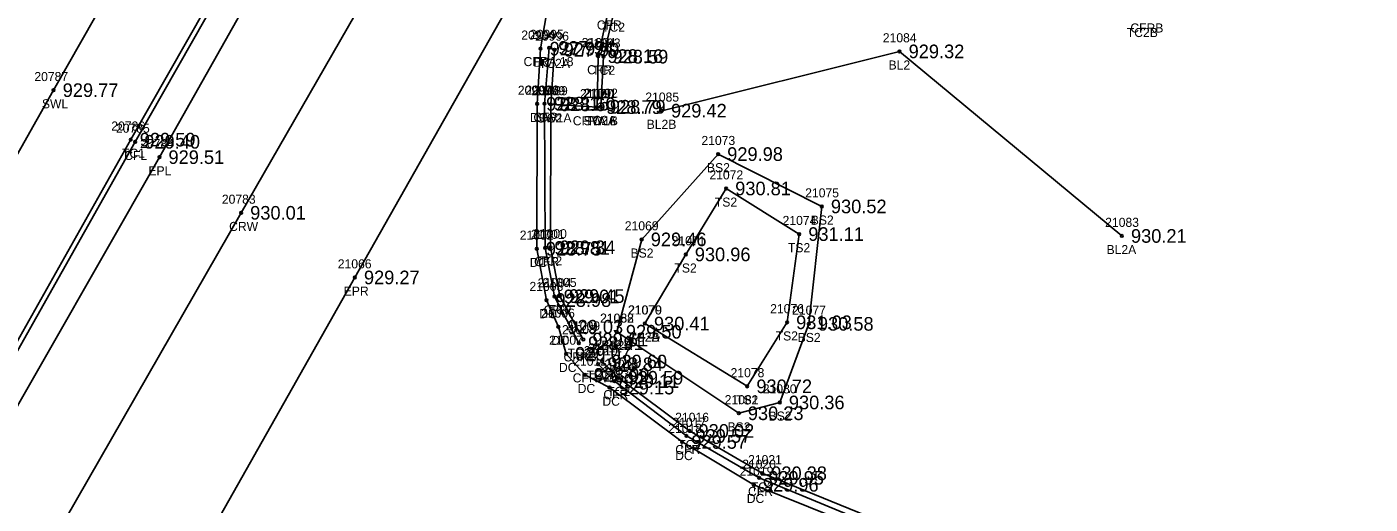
# Model space of a CAD drawing. Extents: x 1576181 to 1577685, y 1099396 to 1101490.
# Drawn here: x 1576724.5 to 1576872.4, y 1100126.4 to 1100179 of the extents above; entities that cross this region are included whole.
import ezdxf

# ---------------------------------------------------------------- set-up
doc = ezdxf.new("R2010")
doc.units = 0
for name, color, linetype in [('RD_DTM_BkLn1', 7, 'Continuous'), ('RD_DTM_BkLn2', 7, 'Continuous'), ('RD_DTM_BkLn_txCode', 7, 'Continuous'), ('RD_EX_Conc', 7, 'Continuous'), ('RD_EX_Conc_txCode', 7, 'Continuous'), ('RD_EX_Road', 7, 'Continuous'), ('RD_EX_Road_txCode', 7, 'Continuous'), ('RD_EX_TX_Conc_ELEV', 7, 'Continuous'), ('RD_EX_TX_Misc_ELEV', 7, 'Continuous'), ('RD_EX_TX_Road_ELEV', 7, 'Continuous'), ('RD_HC_Survey_ELEV', 7, 'Continuous'), ('RD_HC_Survey_txCode', 7, 'Continuous'), ('RD_SMD_Locator', 7, 'Continuous')]:
    doc.layers.add(name, color=color, linetype=linetype)

msp = doc.modelspace()

# ---------------------------------------------------------------- linework, layer by layer
at = {"layer": 'RD_DTM_BkLn1'}
for points in [[(1576435.96, 1099635.47), (1576469.98, 1099685.91), (1576496.51, 1099728.46), (1576522.67, 1099770.85), (1576549.06, 1099813.4), (1576563.36, 1099837.2), (1576575.09, 1099855.95), (1576600.75, 1099898.96), (1576625.57, 1099942.14), (1576652.37, 1099988.91), (1576675.03, 1100029.12), (1576699.51, 1100072.44), (1576723.52, 1100115.7), (1576748.08, 1100158.53), (1576774.13, 1100203.85), (1576797.97, 1100246.52), (1576822.46, 1100289.82), (1576846.93, 1100333.35), (1576871.37, 1100376.46), (1576888.27, 1100406.22)], [(1576845.09, 1100155.98), (1576820.6, 1100176.31), (1576794.43, 1100169.78)]]:
    msp.add_lwpolyline(points, dxfattribs=at)
at = {"layer": 'RD_DTM_BkLn2'}
for points in [[(1576569.71, 1099889.13), (1576574.56, 1099891.34), (1576579.27, 1099894.47), (1576584.19, 1099899.55), (1576592.25, 1099913.59), (1576612.84, 1099949.87), (1576637.54, 1099993.05), (1576637.54, 1099993.05), (1576662.19, 1100036.34), (1576686.67, 1100079.69), (1576711.46, 1100123.12), (1576735.92, 1100166.59), (1576760.76, 1100210.19), (1576785.21, 1100253.55), (1576809.13, 1100296.43), (1576833.85, 1100340.61), (1576852.06, 1100373.52), (1576858.66, 1100385.37)], [(1576787.7, 1100170.21), (1576787.99, 1100175.73), (1576789.09, 1100180.48), (1576790.59, 1100185.09)], [(1576782.61, 1100176.49), (1576782.18, 1100170.48), (1576782.16, 1100154.73), (1576783.18, 1100149.36), (1576785.77, 1100144.57)], [(1576789.46, 1100145.43), (1576792.2, 1100155.6), (1576800.62, 1100165), (1576812.04, 1100159.23), (1576810.61, 1100146.3), (1576807.41, 1100137.64), (1576802.89, 1100136.45), (1576789.46, 1100145.43)], [(1576792.55, 1100146.33), (1576797.05, 1100153.95), (1576801.5, 1100161.21), (1576809.55, 1100156.19), (1576808.21, 1100146.47), (1576803.83, 1100139.42), (1576792.55, 1100146.33)], [(1576787.86, 1100142.15), (1576789.65, 1100140.36), (1576797.46, 1100134.51), (1576805.47, 1100129.84), (1576819.79, 1100124)]]:
    msp.add_lwpolyline(points, dxfattribs=at)
at = {"layer": 'RD_EX_Conc'}
msp.add_line((1576782.18, 1100170.48), (1576787.28, 1100170.17), dxfattribs=at)
for points in [[(1576592.25, 1099913.59), (1576580.2, 1099912.49), (1576604.17, 1099954.86), (1576628.85, 1099997.89), (1576628.85, 1099997.89), (1576652.81, 1100040.47), (1576678.28, 1100085.17), (1576702.19, 1100127.32), (1576727.43, 1100172.04), (1576752.1, 1100215.39), (1576776.49, 1100258.76), (1576788, 1100277.34), (1576801.96, 1100301.42), (1576820.18, 1100348.3), (1576829.19, 1100379.59), (1576833.87, 1100393.41), (1576838.32, 1100402.43), (1576861.82, 1100391.11)], [(1576569.87, 1099888.69), (1576574.84, 1099890.86), (1576574.84, 1099890.86), (1576579.65, 1099894.15), (1576584.72, 1099899.29), (1576592.68, 1099913.3), (1576613.45, 1099949.72), (1576638.02, 1099992.78), (1576638.02, 1099992.78), (1576662.6, 1100036.05), (1576687.14, 1100079.44), (1576711.91, 1100122.93), (1576736.42, 1100166.35), (1576761.24, 1100209.96), (1576785.67, 1100253.17), (1576809.57, 1100296.25), (1576834.31, 1100340.56), (1576852.46, 1100373.22), (1576852.46, 1100373.22), (1576859.24, 1100385.1)], [(1576785.78, 1100195.96), (1576786.17, 1100195.75), (1576783.4, 1100187.6), (1576781.94, 1100181.75), (1576781.06, 1100176.61), (1576780.68, 1100170.53), (1576780.65, 1100154.57), (1576781.71, 1100148.92), (1576783.02, 1100145.98), (1576783.87, 1100143), (1576785.93, 1100140.68), (1576788.65, 1100139.28), (1576796.67, 1100133.29), (1576804.55, 1100128.57), (1576819.43, 1100122.6)], [(1576787.28, 1100170.17), (1576787.42, 1100175.79), (1576788.49, 1100180.72), (1576790.08, 1100185.23)], [(1576782.01, 1100176.69), (1576781.51, 1100170.55), (1576781.58, 1100154.66), (1576782.61, 1100149.32), (1576785.29, 1100144.16)], [(1576787.42, 1100141.85), (1576789.21, 1100140), (1576797.13, 1100133.95), (1576805.14, 1100129.34), (1576819.69, 1100123.32)]]:
    msp.add_lwpolyline(points, dxfattribs=at)
at = {"layer": 'RD_EX_Road'}
for points in [[(1576574.84, 1099890.86), (1576581.17, 1099887.16), (1576595.39, 1099911.97), (1576615.87, 1099948.17), (1576640.56, 1099991.4), (1576640.56, 1099991.4), (1576664.88, 1100034.19), (1576689.84, 1100078.06), (1576714.22, 1100121.19), (1576739.08, 1100164.66), (1576764.15, 1100209.11), (1576788.31, 1100251.8), (1576812.15, 1100294.46), (1576837.06, 1100339.37), (1576855.38, 1100371.53), (1576853.98, 1100372.48), (1576862.98, 1100388.86), (1576865.16, 1100391.95), (1576873.15, 1100402.8), (1576877.45, 1100410.32)], [(1576663.31, 1099979.53), (1576687.43, 1100021.53), (1576712.03, 1100065.1), (1576738.42, 1100112.14), (1576760.61, 1100151.41), (1576785.78, 1100195.96), (1576800.59, 1100221.87), (1576817.54, 1100252.08), (1576858.25, 1100324.63), (1576880.45, 1100364.01), (1576883.5, 1100369.45), (1576896.98, 1100397.71)]]:
    msp.add_lwpolyline(points, dxfattribs=at)
at = {"layer": 'RD_SMD_Locator'}
for centre in [(1576781.06, 1100176.61), (1576782.01, 1100176.69), (1576782.61, 1100176.49), (1576820.6, 1100176.31), (1576787.42, 1100175.79), (1576787.99, 1100175.73), (1576727.43, 1100172.04), (1576780.68, 1100170.53), (1576781.51, 1100170.55), (1576782.18, 1100170.48), (1576782.18, 1100170.48), (1576787.28, 1100170.17), (1576787.28, 1100170.17), (1576787.7, 1100170.21), (1576794.43, 1100169.78), (1576735.92, 1100166.59), (1576736.42, 1100166.35), (1576739.08, 1100164.66), (1576800.62, 1100165), (1576801.5, 1100161.21), (1576748.08, 1100158.53), (1576812.04, 1100159.23), (1576792.2, 1100155.6), (1576809.55, 1100156.19), (1576845.09, 1100155.98), (1576780.65, 1100154.57), (1576781.58, 1100154.66), (1576782.16, 1100154.73), (1576797.05, 1100153.95), (1576760.61, 1100151.41), (1576781.71, 1100148.92), (1576782.61, 1100149.32), (1576783.18, 1100149.36), (1576783.02, 1100145.98), (1576789.46, 1100145.43), (1576789.46, 1100145.43), (1576792.55, 1100146.33), (1576792.55, 1100146.33), (1576808.21, 1100146.47), (1576810.61, 1100146.3), (1576785.29, 1100144.16), (1576785.77, 1100144.57), (1576783.87, 1100143), (1576785.93, 1100140.68), (1576787.42, 1100141.85), (1576787.86, 1100142.15), (1576788.65, 1100139.28), (1576789.21, 1100140), (1576789.65, 1100140.36), (1576803.83, 1100139.42), (1576802.89, 1100136.45), (1576807.41, 1100137.64), (1576796.67, 1100133.29), (1576797.13, 1100133.95), (1576797.46, 1100134.51), (1576805.14, 1100129.34), (1576805.47, 1100129.84), (1576804.55, 1100128.57)]:
    msp.add_circle(centre, 0.15, dxfattribs=at)

# ---------------------------------------------------------------- texts
at = {"layer": 'RD_DTM_BkLn_txCode'}
for s, p in [('21084', (1576818.76, 1100177.31)), ('BL2', (1576819.39, 1100174.31)), ('21085', (1576792.6, 1100170.78)), ('BL2B', (1576792.75, 1100167.78)), ('21073', (1576798.78, 1100166)), ('BS2', (1576799.39, 1100163)), ('21072', (1576799.66, 1100162.21)), ('TS2', (1576800.26, 1100159.21)), ('21075', (1576810.21, 1100160.23)), ('21069', (1576790.34, 1100156.6)), ('21074', (1576807.72, 1100157.19)), ('BS2', (1576810.82, 1100157.23)), ('21083', (1576843.25, 1100156.98)), ('21071', (1576795.5, 1100154.95)), ('BS2', (1576790.97, 1100153.6)), ('TS2', (1576808.31, 1100154.19)), ('BL2A', (1576843.4, 1100153.98)), ('TS2', (1576795.81, 1100151.95)), ('21070', (1576790.68, 1100147.33)), ('21079', (1576790.72, 1100147.33)), ('21076', (1576806.35, 1100147.47)), ('21077', (1576808.77, 1100147.3)), ('21068', (1576787.61, 1100146.43)), ('21082', (1576787.63, 1100146.43)), ('TS2A', (1576790.82, 1100144.33)), ('TS2B', (1576790.83, 1100144.33)), ('TS2', (1576806.96, 1100144.47)), ('BS2', (1576809.38, 1100144.3)), ('BS2A', (1576787.75, 1100143.43)), ('BS2B', (1576787.76, 1100143.43)), ('21078', (1576801.99, 1100140.42)), ('21080', (1576805.54, 1100138.64)), ('21081', (1576801.34, 1100137.45)), ('TS2', (1576802.58, 1100137.42)), ('BS2', (1576806.18, 1100135.64)), ('BS2', (1576801.66, 1100134.45))]:
    msp.add_text(s, height=1, dxfattribs=at).set_placement(p)
at = {"layer": 'RD_EX_Conc_txCode'}
for s, p in [('CFR', (1576787.26, 1100178.72)), ('TC2', (1576787.84, 1100178.48)), ('CFRB', (1576846.02, 1100178.39)), ('20994', (1576778.94, 1100177.61)), ('20995', (1576779.89, 1100177.69)), ('20996', (1576780.47, 1100177.49)), ('TC2B', (1576845.63, 1100177.89)), ('21094', (1576785.59, 1100176.79)), ('21093', (1576786.15, 1100176.73)), ('CFRA 18', (1576779.19, 1100174.69)), ('DC', (1576780.28, 1100174.61)), ('TC2A', (1576780.88, 1100174.49)), ('20787', (1576725.31, 1100173.04)), ('CFR', (1576786.19, 1100173.79)), ('TC2', (1576786.75, 1100173.73)), ('20997', (1576778.56, 1100171.53)), ('20998', (1576779.39, 1100171.55)), ('20999', (1576780.06, 1100171.48)), ('21089', (1576780.34, 1100171.48)), ('21090', (1576785.41, 1100171.17)), ('21091', (1576785.73, 1100171.17)), ('21092', (1576785.86, 1100171.21)), ('SWL', (1576726.14, 1100170.04)), ('DC', (1576779.9, 1100168.53)), ('CFR', (1576780.28, 1100168.55)), ('SW1A', (1576780.68, 1100168.48)), ('TC2', (1576780.93, 1100168.48)), ('CFRA 6', (1576784.61, 1100168.17)), ('SW1B', (1576785.8, 1100168.17)), ('TC2A', (1576785.97, 1100168.21)), ('20786', (1576733.78, 1100167.59)), ('20785', (1576734.3, 1100167.35)), ('TC1', (1576734.96, 1100164.59)), ('CFL', (1576735.21, 1100164.35)), ('21002', (1576778.77, 1100155.57)), ('21001', (1576779.99, 1100155.66)), ('21000', (1576780.24, 1100155.73)), ('DC', (1576779.87, 1100152.57)), ('CFR', (1576780.35, 1100152.66)), ('TC2', (1576780.91, 1100152.73)), ('21004', (1576780.74, 1100150.32)), ('21005', (1576781.31, 1100150.36)), ('21003', (1576779.84, 1100149.92)), ('CFR', (1576781.39, 1100147.32)), ('TC2', (1576781.94, 1100147.36)), ('DC', (1576780.93, 1100146.92)), ('21006', (1576781.12, 1100146.98)), ('21008', (1576783.42, 1100145.16)), ('21009', (1576783.9, 1100145.57)), ('21007', (1576782, 1100144)), ('DC', (1576782.24, 1100143.98)), ('21010', (1576785.83, 1100142.85)), ('21012', (1576786.31, 1100143.15)), ('CFRB', (1576783.59, 1100142.16)), ('TC2B', (1576784.05, 1100142.57)), ('21011', (1576784.66, 1100141.68)), ('21015', (1576788.1, 1100141.36)), ('DC', (1576783.09, 1100141)), ('CFRA 18', (1576784.6, 1100139.85)), ('TC2A', (1576786.13, 1100140.15)), ('21013', (1576787.1, 1100140.28)), ('21014', (1576787.66, 1100141)), ('DC', (1576785.15, 1100138.68)), ('TC2', (1576788.41, 1100138.36)), ('DC', (1576787.87, 1100137.28)), ('CFR', (1576787.98, 1100138)), ('21016', (1576795.89, 1100135.51)), ('21018', (1576795.12, 1100134.29)), ('21017', (1576795.58, 1100134.95)), ('TC2', (1576796.22, 1100132.51)), ('CFR', (1576795.9, 1100131.95)), ('DC', (1576795.89, 1100131.29)), ('21019', (1576802.99, 1100129.57)), ('21020', (1576803.27, 1100130.34)), ('21021', (1576803.92, 1100130.84)), ('DC', (1576803.77, 1100126.57)), ('CFR', (1576803.91, 1100127.34)), ('TC2', (1576804.22, 1100127.84))]:
    msp.add_text(s, height=1, dxfattribs=at).set_placement(p)
at = {"layer": 'RD_EX_Road_txCode'}
for s, p in [('20784', (1576736.96, 1100165.66)), ('EPL', (1576737.87, 1100162.66)), ('21066', (1576758.73, 1100152.41)), ('EPR', (1576759.38, 1100149.41))]:
    msp.add_text(s, height=1, dxfattribs=at).set_placement(p)
at = {"layer": 'RD_EX_TX_Conc_ELEV'}
for s, p in [('927.92', (1576782.06, 1100175.86)), ('927.94', (1576783.01, 1100175.94)), ('927.99', (1576783.61, 1100175.74)), ('928.16', (1576788.42, 1100175.04)), ('928.59', (1576788.99, 1100174.98)), ('929.77', (1576728.43, 1100171.29)), ('928.11', (1576781.68, 1100169.78)), ('928.15', (1576782.51, 1100169.8)), ('928.60', (1576783.18, 1100169.73)), ('928.60', (1576783.18, 1100169.73)), ('928.79', (1576788.28, 1100169.42)), ('928.79', (1576788.28, 1100169.42)), ('928.79', (1576788.7, 1100169.46)), ('929.59', (1576736.92, 1100165.84)), ('929.40', (1576737.42, 1100165.6)), ('928.75', (1576781.65, 1100153.82)), ('928.81', (1576782.58, 1100153.91)), ('929.34', (1576783.16, 1100153.98)), ('929.01', (1576783.61, 1100148.57)), ('929.45', (1576784.18, 1100148.61)), ('928.98', (1576782.71, 1100148.17)), ('929.03', (1576784.02, 1100145.23)), ('929.61', (1576786.77, 1100143.82)), ('928.91', (1576786.29, 1100143.41)), ('929.07', (1576784.87, 1100142.25)), ('928.84', (1576788.42, 1100141.1)), ('929.60', (1576788.86, 1100141.4)), ('928.99', (1576786.93, 1100139.93)), ('929.59', (1576790.65, 1100139.61)), ('929.15', (1576789.65, 1100138.53)), ('929.11', (1576790.21, 1100139.25)), ('930.02', (1576798.46, 1100133.76)), ('929.57', (1576797.67, 1100132.54)), ('929.57', (1576798.13, 1100133.2)), ('930.38', (1576806.47, 1100129.09)), ('929.96', (1576805.55, 1100127.82)), ('929.95', (1576806.14, 1100128.59))]:
    msp.add_text(s, height=1.5, dxfattribs=at).set_placement(p)
at = {"layer": 'RD_EX_TX_Misc_ELEV'}
for s, p in [('929.32', (1576821.6, 1100175.56)), ('929.42', (1576795.43, 1100169.03)), ('929.98', (1576801.62, 1100164.25)), ('930.81', (1576802.5, 1100160.46)), ('930.52', (1576813.04, 1100158.48)), ('929.46', (1576793.2, 1100154.85)), ('931.11', (1576810.55, 1100155.44)), ('930.21', (1576846.09, 1100155.23)), ('930.96', (1576798.05, 1100153.2)), ('930.41', (1576793.55, 1100145.58)), ('930.41', (1576793.55, 1100145.58)), ('931.03', (1576809.21, 1100145.72)), ('930.58', (1576811.61, 1100145.55)), ('929.50', (1576790.46, 1100144.68)), ('929.50', (1576790.46, 1100144.68)), ('930.72', (1576804.83, 1100138.67)), ('930.36', (1576808.41, 1100136.89)), ('930.23', (1576803.89, 1100135.7))]:
    msp.add_text(s, height=1.5, dxfattribs=at).set_placement(p)
at = {"layer": 'RD_EX_TX_Road_ELEV'}
for s, p in [('929.51', (1576740.08, 1100163.91)), ('929.27', (1576761.61, 1100150.66))]:
    msp.add_text(s, height=1.5, dxfattribs=at).set_placement(p)
at = {"layer": 'RD_HC_Survey_ELEV'}
msp.add_text('930.01', height=1.5, dxfattribs=at).set_placement((1576749.08, 1100157.78))
at = {"layer": 'RD_HC_Survey_txCode'}
for s, p in [('20783', (1576745.96, 1100159.53)), ('CRW', (1576746.76, 1100156.53))]:
    msp.add_text(s, height=1, dxfattribs=at).set_placement(p)

doc.saveas('drawing.dxf')
